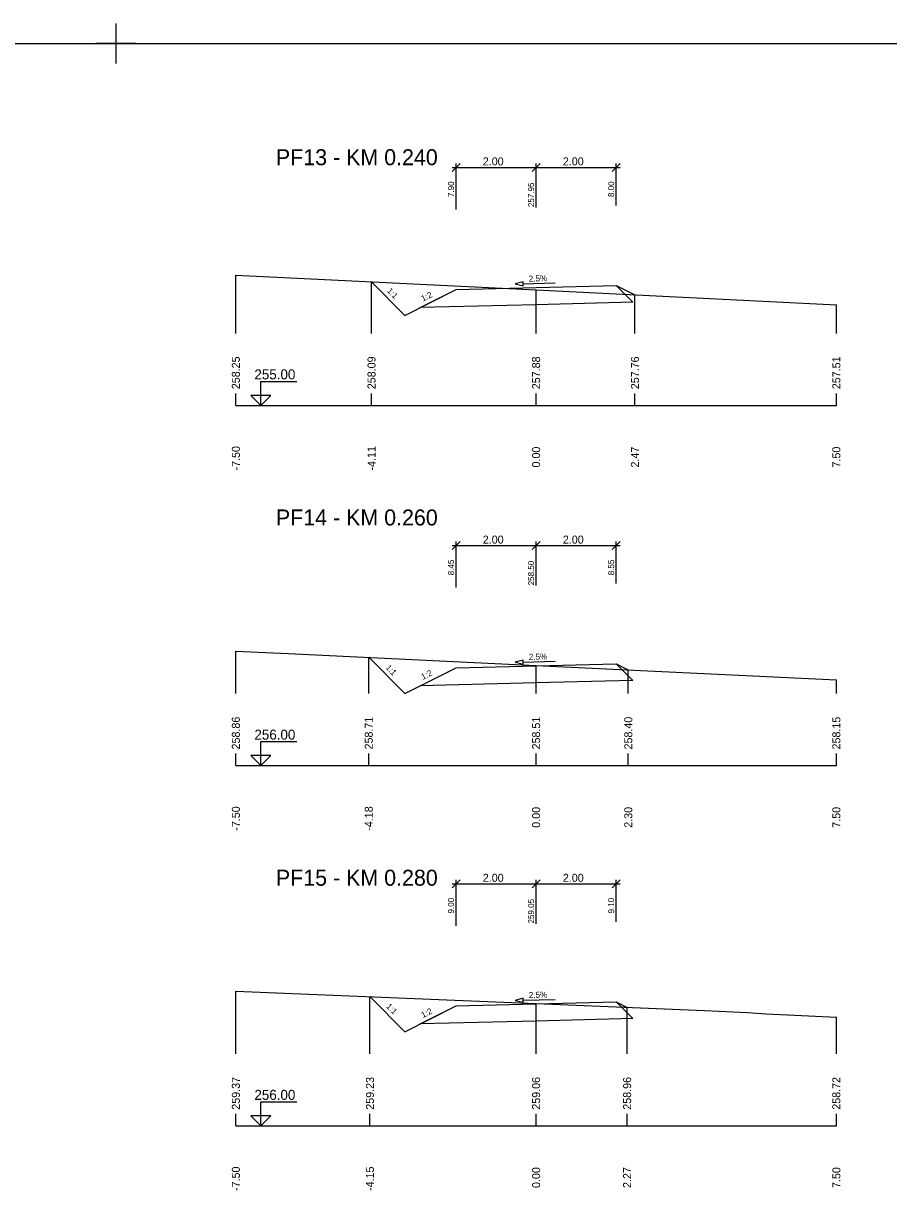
# Model space of a CAD drawing. Extents: x -5 to 1895, y -2 to 602.
# Drawn here: x 817 to 1033, y 308.1 to 602.4 of the extents above; entities that cross this region are included whole.
import ezdxf

# ---------------------------------------------------------------- set-up
doc = ezdxf.new("R2010")
doc.units = 0
for name, color, linetype in [('KOTA', 7, 'Continuous'), ('KOTA_DELKY', 7, 'Continuous'), ('KOTA_DELKY_CONT', 7, 'Continuous'), ('NS_TELESO_VOZOVKY', 7, 'Continuous'), ('NS_V_PF', 7, 'Continuous'), ('REZY_PF_PUVODNI', 7, 'Continuous'), ('SESTAVY_REZU_PF', 7, 'Continuous'), ('SKLON', 7, 'Continuous'), ('SVK', 7, 'Continuous')]:
    doc.layers.add(name, color=color, linetype=linetype)

msp = doc.modelspace()

# ---------------------------------------------------------------- linework, layer by layer
for p, q in [((840, 602.39), (840, 592.39)), ((840, 602.39), (840, 592.39)), ((840, 602.39), (840, 592.39)), ((840, 602.39), (840, 592.39)), ((840, 602.39), (840, 592.39)), ((840, 602.39), (840, 592.39)), ((840, 602.39), (840, 592.39)), ((840, 602.39), (840, 592.39)), ((840, 602.39), (840, 592.39)), ((840, 602.39), (840, 592.39)), ((840, 602.39), (840, 592.39)), ((840, 602.39), (840, 592.39)), ((840, 602.39), (840, 592.39)), ((840, 602.39), (840, 592.39)), ((840, 602.39), (840, 592.39)), ((840, 602.39), (840, 592.39)), ((840, 602.39), (840, 592.39)), ((840, 602.39), (840, 592.39)), ((845, 597.39), (835, 597.39)), ((845, 597.39), (835, 597.39)), ((845, 597.39), (835, 597.39)), ((845, 597.39), (835, 597.39)), ((845, 597.39), (835, 597.39)), ((845, 597.39), (835, 597.39)), ((845, 597.39), (835, 597.39)), ((845, 597.39), (835, 597.39)), ((845, 597.39), (835, 597.39)), ((845, 597.39), (835, 597.39)), ((845, 597.39), (835, 597.39)), ((845, 597.39), (835, 597.39)), ((845, 597.39), (835, 597.39)), ((845, 597.39), (835, 597.39)), ((845, 597.39), (835, 597.39)), ((845, 597.39), (835, 597.39)), ((845, 597.39), (835, 597.39)), ((845, 597.39), (835, 597.39))]:
    msp.add_line(p, q)
msp.add_lwpolyline([(0, 597.39), (1890, 597.39), (1890, 3.39), (0, 3.39)], close=True)
at = {"layer": 'KOTA'}
for points in [[(876.22, 509.5), (873.72, 509.5), (876.22, 507), (876.22, 513), (885.22, 513)], [(876.22, 507), (878.72, 509.5), (876.22, 509.5)], [(876.22, 419.5), (873.72, 419.5), (876.22, 417), (876.22, 423), (885.22, 423)], [(876.22, 417), (878.72, 419.5), (876.22, 419.5)], [(876.22, 329.5), (873.72, 329.5), (876.22, 327), (876.22, 333), (885.22, 333)], [(876.22, 327), (878.72, 329.5), (876.22, 329.5)]]:
    msp.add_lwpolyline(points, dxfattribs=at)
at = {"layer": 'KOTA_DELKY'}
for points in [[(924, 565.46), (926, 567.46)], [(924, 566.46), (946, 566.46)], [(925, 555.96), (925, 567.46)], [(944, 565.46), (946, 567.46)], [(944, 565.46), (946, 567.46)], [(944, 566.46), (966, 566.46)], [(945, 556.46), (945, 567.46)], [(945, 556.46), (945, 567.46)], [(964, 565.46), (966, 567.46)], [(965, 556.96), (965, 567.46)], [(924, 470.97), (926, 472.97)], [(924, 471.97), (946, 471.97)], [(925, 461.47), (925, 472.97)], [(944, 470.97), (946, 472.97)], [(944, 470.97), (946, 472.97)], [(944, 471.97), (966, 471.97)], [(945, 461.97), (945, 472.97)], [(945, 461.97), (945, 472.97)], [(964, 470.97), (966, 472.97)], [(965, 462.47), (965, 472.97)], [(924, 386.48), (926, 388.48)], [(925, 376.98), (925, 388.48)], [(944, 386.48), (946, 388.48)], [(944, 386.48), (946, 388.48)], [(945, 377.48), (945, 388.48)], [(945, 377.48), (945, 388.48)], [(964, 386.48), (966, 388.48)], [(965, 377.98), (965, 388.48)], [(924, 387.48), (946, 387.48)], [(944, 387.48), (966, 387.48)]]:
    msp.add_lwpolyline(points, dxfattribs=at)
at = {"layer": 'NS_TELESO_VOZOVKY'}
for points in [[(945, 536.46), (965, 536.96), (965, 536.96), (969.2, 532.76), (945, 532.16), (916.05, 531.43), (925, 535.96), (925, 535.96), (945, 536.46)], [(945, 441.97), (965, 442.47), (965, 442.47), (969.2, 438.27), (945, 437.67), (916.05, 436.95), (925, 441.47), (925, 441.47), (945, 441.97)], [(945, 357.48), (965, 357.98), (965, 357.98), (969.2, 353.79), (945, 353.18), (916.05, 352.46), (925, 356.98), (925, 356.98), (945, 357.48)]]:
    msp.add_lwpolyline(points, dxfattribs=at)
at = {"layer": 'NS_V_PF'}
for points in [[(903.89, 537.86), (912.19, 529.48), (925, 535.96), (925, 535.96), (945, 536.46), (965, 536.96), (965, 536.96), (969.7, 534.61)], [(903.2, 444.08), (912.19, 434.99), (925, 441.47), (925, 441.47), (945, 441.97), (965, 442.47), (965, 442.47), (968.03, 440.95)], [(903.5, 359.29), (912.19, 350.51), (925, 356.98), (925, 356.98), (945, 357.48), (965, 357.98), (965, 357.98), (967.74, 356.61)]]:
    msp.add_lwpolyline(points, dxfattribs=at)
at = {"layer": 'REZY_PF_PUVODNI'}
for points in [[(870, 539.54), (945, 535.83), (1020, 532.12)], [(870, 445.59), (883.07, 445.05), (945, 442.06), (1020, 438.45)], [(870, 360.68), (945, 357.56), (987.07, 355.81), (997.82, 355.32), (1002.46, 354.99), (1007.81, 354.78), (1020, 354.16)]]:
    msp.add_lwpolyline(points, dxfattribs=at)
at = {"layer": 'SESTAVY_REZU_PF'}
for points in [[(870, 507), (1020, 507)], [(870, 417), (1020, 417)], [(870, 327), (1020, 327)]]:
    msp.add_lwpolyline(points, dxfattribs=at)
at = {"layer": 'SKLON'}
for points in [[(941.79, 537.88), (939.8, 537.33), (941.81, 536.88), (941.79, 537.88)], [(941.8, 537.38), (949.8, 537.58)], [(941.79, 443.39), (939.8, 442.84), (941.81, 442.39), (941.79, 443.39)], [(941.8, 442.89), (949.8, 443.09)], [(941.79, 358.9), (939.8, 358.35), (941.81, 357.9), (941.79, 358.9)], [(941.8, 358.4), (949.8, 358.6)]]:
    msp.add_lwpolyline(points, dxfattribs=at)
at = {"layer": 'SVK'}
for points in [[(870, 525), (870, 539.54)], [(903.89, 525), (903.89, 537.86)], [(945, 525), (945, 535.83)], [(969.7, 525), (969.7, 534.61)], [(1020, 525), (1020, 532.12)], [(870, 507), (870, 510)], [(903.89, 507), (903.89, 510)], [(945, 507), (945, 510)], [(969.7, 507), (969.7, 510)], [(1020, 507), (1020, 510)], [(870, 435), (870, 445.59)], [(903.2, 435), (903.2, 444.08)], [(945, 435), (945, 442.06)], [(968.03, 435), (968.03, 440.95)], [(1020, 435), (1020, 438.45)], [(870, 417), (870, 420)], [(903.2, 417), (903.2, 420)], [(945, 417), (945, 420)], [(968.03, 417), (968.03, 420)], [(1020, 417), (1020, 420)], [(870, 345), (870, 360.68)], [(903.5, 345), (903.5, 359.29)], [(945, 345), (945, 357.56)], [(967.74, 345), (967.74, 356.61)], [(1020, 345), (1020, 354.16)], [(870, 327), (870, 330)], [(903.5, 327), (903.5, 330)], [(945, 327), (945, 330)], [(967.74, 327), (967.74, 330)], [(1020, 327), (1020, 330)]]:
    msp.add_lwpolyline(points, dxfattribs=at)

# ---------------------------------------------------------------- texts
at = {"layer": 'KOTA'}
for s, p in [('255.00', (874.64, 513.5)), ('256.00', (874.64, 423.5)), ('256.00', (874.64, 333.5))]:
    msp.add_text(s, height=2.5, dxfattribs=at).set_placement(p)
at = {"layer": 'KOTA_DELKY'}
for p in [(931.69, 566.96), (951.69, 566.96), (931.69, 472.47), (951.69, 472.47), (931.69, 387.98), (951.69, 387.98)]:
    msp.add_text('2.00', height=2, dxfattribs=at).set_placement(p)
at = {"layer": 'KOTA_DELKY_CONT'}
for s, p in [('7.90', (924.5, 559.05)), ('257.95', (944.5, 556.53)), ('8.00', (964.5, 559.05)), ('8.45', (924.5, 464.56)), ('258.50', (944.5, 462.05)), ('8.55', (964.5, 464.56)), ('9.00', (924.5, 380.07)), ('259.05', (944.5, 377.56)), ('9.10', (964.5, 380.07))]:
    msp.add_text(s, height=1.5, rotation=90, dxfattribs=at).set_placement(p)
at = {"layer": 'SESTAVY_REZU_PF'}
for s, p in [('PF13 - KM 0.240', (880, 567)), ('PF14 - KM 0.260', (880, 477)), ('PF15 - KM 0.280', (880, 387))]:
    msp.add_text(s, height=4, dxfattribs=at).set_placement(p)
at = {"layer": 'SKLON'}
for s, rotation, p in [('2.5%', 1.4321, (943.2, 537.91)), ('1:1', 314.7121, (907.64, 535.49)), ('1:2', 26.8233, (916.74, 532.9)), ('2.5%', 1.4321, (943.2, 443.42)), ('1:1', 314.7121, (907.3, 441.36)), ('1:2', 26.8233, (916.74, 438.41)), ('2.5%', 1.4321, (943.2, 358.94)), ('1:1', 314.7121, (907.45, 356.72)), ('1:2', 26.8233, (916.74, 353.92))]:
    msp.add_text(s, height=1.5, rotation=rotation, dxfattribs=at).set_placement(p)
at = {"layer": 'SVK'}
for s, p in [(' 258.25', (871, 510.3)), (' 258.09', (904.89, 510.3)), (' 257.88', (946, 510.3)), (' 257.76', (970.7, 510.3)), (' 257.51', (1021, 510.3)), (' -7.50', (871, 490)), (' -4.11', (904.89, 490)), ('  0.00', (946, 490)), ('  2.47', (970.7, 490)), ('  7.50', (1021, 490)), (' 258.86', (871, 420.3)), (' 258.71', (904.2, 420.3)), (' 258.51', (946, 420.3)), (' 258.40', (969.03, 420.3)), (' 258.15', (1021, 420.3)), (' -7.50', (871, 400)), (' -4.18', (904.2, 400)), ('  0.00', (946, 400)), ('  2.30', (969.03, 400)), ('  7.50', (1021, 400)), (' 259.37', (871, 330.3)), (' 259.23', (904.5, 330.3)), (' 259.06', (946, 330.3)), (' 258.96', (968.74, 330.3)), (' 258.72', (1021, 330.3)), (' -7.50', (871, 310)), (' -4.15', (904.5, 310)), ('  0.00', (946, 310)), ('  2.27', (968.74, 310)), ('  7.50', (1021, 310))]:
    msp.add_text(s, height=2, rotation=90, dxfattribs=at).set_placement(p)

doc.saveas('drawing.dxf')
